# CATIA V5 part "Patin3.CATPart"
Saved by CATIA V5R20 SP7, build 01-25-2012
Part number: Patin3
Bounding box of the stored display mesh (mm): x 0 to 15, y -52.982 to 5.976, z 16.046 to 116.995
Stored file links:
  J:\ACHTUNG2\Patin3.CATPart
  J:\ACHTUNG2\cmilovidof.CATProduct
  J:\ACHTUNG2\Equerre7.CATPart
  J:\ACHTUNG\IAO non optimisé fini et qui marche à rendre\Patin3.CATPart
  J:\ACHTUNG2\Patin2.CATPart
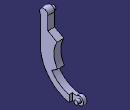
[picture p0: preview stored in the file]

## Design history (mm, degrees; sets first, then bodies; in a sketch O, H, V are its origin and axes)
External parameters (linked from other documents)
  External.diam_roue = 64 mm
Set1
  Plane1: linked copy from another document
  Line1 "Axe_Patin2Patin1": linked copy from another document
  Line2 "Axe_Equerre7Patin3": linked copy from another document
  Point1: linked copy from another document
  DatumCurve1: linked copy from another document
Body1 (main body)
  Sketch1 on Plane1, origin (5, 0, 0), H (0, 1, 0), V (0, 0, 1)
    arc A1 centre (0, 22) radius 6 from (-4.3493, 26.1332) to (-2.2168, 16.4245) cw
    line L1 (-26.8375, 50.5716) -> (-35.3014, 45.075)
    construction line L2 (0, 68) -> (-26.8375, 50.5716)
    arc A2 centre (-47, 111) radius 6 from (-51.6231, 107.1755) to (-41.0001, 110.9687) cw
    line L3 (-27.5084, 84.349) -> (-41.0001, 91.7955)
    axis line L4 (0, 68) -> (-26.9913, 82.8973)
    point P1 (0, 68)
    arc A3 centre (0, 68) radius 51.6231 from (-2.2168, 16.4245) to (-51.6231, 68) cw
    line L5 (-51.6231, 68) -> (-51.6231, 107.1755)
    point P2 (-51.6231, 107.1755)
    point P3 (-51.6231, 107.1755)
    point P4 (-51.6231, 68)
    point P5 (-51.6231, 68)
    point P6 (-35.3014, 45.075)
    point P7 (-35.3014, 45.075)
    point P8 (-4.3493, 26.1332)
    point P9 (-4.3493, 26.1332)
    construction line L6 (-41.0001, 110.9687) -> (-42.0613, 66.3896)
    construction arc A4 centre (0, 68) radius 42.0921 from (-4.3493, 26.1332) to (-42.0613, 66.3896) cw
    arc A5 centre (0, 68) radius 32 from (-26.8375, 50.5716) to (-27.5084, 84.349) cw
    line L7 (-41.0001, 110.9687) -> (-41.0001, 91.7955)
    arc A6 centre (0, 68) radius 42.0921 from (-4.3493, 26.1332) to (-35.3014, 45.075) cw
    reference projected point E1 (0, 22) from Line1
    reference projected point E2 (-47, 111) from Line2
    reference projected point E3 (0, 22) from Point1
    radius A1 = 6 {= External.diam_roue *6/64}
    angle L2 L4 = 61.8956
    radius A5 = 32 {= External.diam_roue *32/64}
    radius A2 = 6 {= 6*External.diam_roue /64}
    distance A6 A3 = 9.531 {= 9.531*External.diam_roue /64}
    distance P1 E3 = 46
    angle L1 V = 57
    distance L7 L5 = 10.623 {= 10.623*External.diam_roue /64}
    parallelism: L2 L1, L4 L3
    tangency: L5 A3
    vertical: L5 V
    coincidence: P3 P2, P5 P4, P7 P6, P9 P8, P1 V
    concentricity: A1 E1, A2 E2
  Pad1: profile Sketch1, direction (1, 0, 0), length 10
  Sketch2 on start face of Pad1, origin (5, 0, 0), H (0, -1, 0), V (0, 0, 1)
    circle A1 centre (47, 111) radius 3
    reference projected arc E1 centre (47, 111) radius 6 from (41.7867, 113.9701) to (49.3785, 116.5084) ccw from edge of DatumCurve1
    radius A1 = 3 {= 3*External.diam_roue /64}
    concentricity: E1 A1
  Pad2: profile Sketch2, direction (-1, 0, 0), length 5
  Sketch3 on end face of Pad1, origin (15, 0, 0), H (0, 1, 0), V (0, 0, 1)
    line L1 (10, 32) -> (-10, 32)
    line L2 (-10, 32) -> (-10, 12)
    line L3 (-10, 12) -> (10, 12)
    line L4 (10, 12) -> (10, 32)
    reference projected point E1 (0, 22) from Point1
    reference projected point E2 (0, 22) from Point1
    distance L2 L4 = 20
    distance L3 L1 = 20
    distance L4 E1 = 10
    distance E2 L1 = 10
    horizontal: L1 H, L3 H
    vertical: L2 V, L4 V
  Pocket1: profile Sketch3, direction (-1, 0, 0), length 5
  Sketch4 on end face of Pocket1, origin (10, 0, 0), H (0, 1, 0), V (0, 0, 1)
    circle A1 centre (0, 22) radius 3
    reference projected arc E1 centre (0, 22) radius 6 from (-2.2168, 16.4245) to (-4.3493, 26.1332) ccw from edge [face of Pad1 from Sketch1.A1 | end face of Pocket1]
    radius A1 = 3 {= 3*External.diam_roue /64}
    concentricity: A1 E1
  Pad3: profile Sketch4, direction (1, 0, 0), length 5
